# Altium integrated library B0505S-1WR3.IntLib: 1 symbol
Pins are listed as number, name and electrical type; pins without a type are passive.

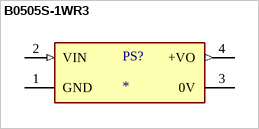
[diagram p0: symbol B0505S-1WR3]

## B0505S-1WR3
designator PS?
Isolated Module DC DC Converter 1 Output 5V 200mA 4.5V - 5.5V Input; MF: Mornsun America, LLC; MP: B0505S-1WR3
footprint CONV_B0505S-1WR3
pins: 1 GND (power), 2 VIN (in), 3 0V, 4 +VO (out)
